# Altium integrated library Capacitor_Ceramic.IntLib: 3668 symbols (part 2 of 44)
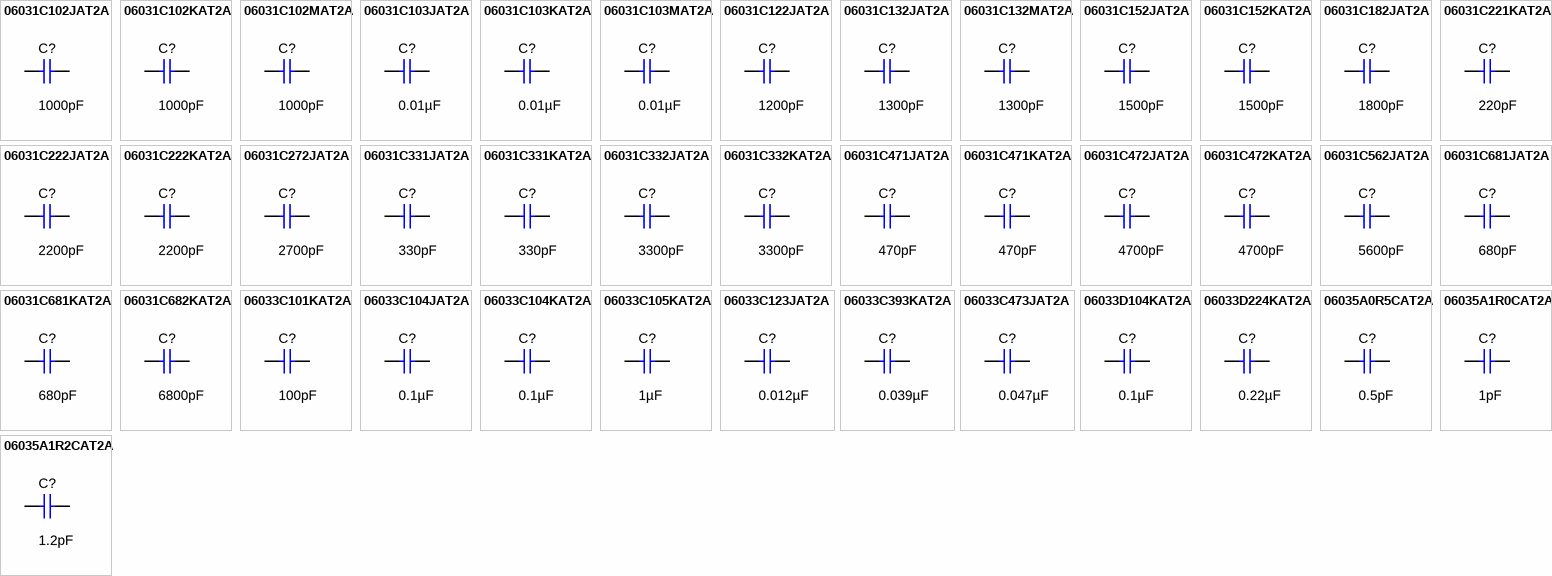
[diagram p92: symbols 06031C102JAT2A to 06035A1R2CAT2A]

## 06031C103MAT2A
designator C?  ValueDisplayed: 0.01µF  (hidden comment: 06031C103MAT2A)
CAP, CERM, 0.01 µF, 100 V,+/- 20%, X7R, 0603; Manufacturer: AVX; Polarized: N; CompType: Capacitor; Value: 0.01uF; U/M: EA; Cap_F: 0.00000001; Tolerance_%: 20; ESR_ohm: 0.098; Value1: 0.098 ohm; VDC_V: 100; Value2: 100V; TaMin_C: -55; TaMax_C: 125; Cap_Case: 0603; SizeArea_mm2: 1.28; SizeAreaWB_mm2: 4.68; SizeX_mm: 1.6; SizeY_mm: 0.8; SizeZ_mm: 1; AEC Category: Q200; Green_Lifecycle: Active; Green_REACh: Passed
signal-integrity model Cap
simulation model Cap
footprint 0603
footprint 0603M
footprint 0603L
footprint 0603_HV
footprint 0603S
pins: 1, 2

## 06031C122JAT2A
designator C?  ValueDisplayed: 1200pF  (hidden comment: 06031C122JAT2A)
CAP, CERM, 1200 pF, 100 V,+/- 5%, X7R, 0603; Manufacturer: AVX; Polarized: N; CompType: Capacitor; Value: 1200pF; U/M: EA; Cap_F: 0.0000000012; Tolerance_%: 5; ESR_ohm: 0.254; Value1: 0.254 ohm; VDC_V: 100; Value2: 100V; TaMin_C: -55; TaMax_C: 125; Cap_Case: 0603; SizeArea_mm2: 1.28; SizeAreaWB_mm2: 4.68; SizeX_mm: 1.6; SizeY_mm: 0.8; SizeZ_mm: 1; AEC Category: Q200; Green_Lifecycle: Not Set; Green_REACh: Incomplete
signal-integrity model Cap
simulation model Cap
footprint 0603
footprint 0603M
footprint 0603L
footprint 0603_HV
footprint 0603S
pins: 1, 2

## 06031C132JAT2A
designator C?  ValueDisplayed: 1300pF  (hidden comment: 06031C132JAT2A)
CAP, CERM, 1300 pF, 100 V,+/- 5%, X7R, 0603; Manufacturer: AVX; Polarized: N; CompType: Capacitor; Value: 1300pF; U/M: EA; Cap_F: 0.0000000013; Tolerance_%: 5; VDC_V: 100; Value2: 100V; TaMin_C: -55; TaMax_C: 125; Cap_Case: 0603; SizeArea_mm2: 1.28; SizeAreaWB_mm2: 4.68; SizeX_mm: 1.6; SizeY_mm: 0.8; SizeZ_mm: 1; AEC Category: Q200; Green_Lifecycle: Not Set; Green_REACh: Incomplete
signal-integrity model Cap
simulation model Cap
footprint 0603
footprint 0603M
footprint 0603L
footprint 0603_HV
footprint 0603S
pins: 1, 2

## 06031C132MAT2A
designator C?  ValueDisplayed: 1300pF  (hidden comment: 06031C132MAT2A)
CAP, CERM, 1300 pF, 100 V,+/- 20%, X7R, 0603; Manufacturer: AVX; Polarized: N; CompType: Capacitor; Value: 1300pF; U/M: EA; Cap_F: 0.0000000013; Tolerance_%: 20; VDC_V: 100; Value2: 100V; TaMin_C: -55; TaMax_C: 125; Cap_Case: 0603; SizeArea_mm2: 1.28; SizeAreaWB_mm2: 4.68; SizeX_mm: 1.6; SizeY_mm: 0.8; SizeZ_mm: 1; AEC Category: Q200; Green_Lifecycle: Not Set; Green_REACh: Incomplete
signal-integrity model Cap
simulation model Cap
footprint 0603
footprint 0603M
footprint 0603L
footprint 0603_HV
footprint 0603S
pins: 1, 2

## 06031C152JAT2A
designator C?  ValueDisplayed: 1500pF  (hidden comment: 06031C152JAT2A)
CAP, CERM, 1500 pF, 100 V,+/- 5%, X7R, 0603; Manufacturer: AVX; Polarized: N; CompType: Capacitor; Value: 1500pF; U/M: EA; Cap_F: 0.0000000015; Tolerance_%: 5; ESR_ohm: 0.229; Value1: 0.229 ohm; VDC_V: 100; Value2: 100V; TaMin_C: -55; TaMax_C: 125; Cap_Case: 0603; SizeArea_mm2: 1.28; SizeAreaWB_mm2: 4.68; SizeX_mm: 1.6; SizeY_mm: 0.8; SizeZ_mm: 1; AEC Category: Q200; Green_Lifecycle: Active; Green_REACh: Passed
signal-integrity model Cap
simulation model Cap
footprint 0603
footprint 0603M
footprint 0603L
footprint 0603_HV
footprint 0603S
pins: 1, 2

## 06031C152KAT2A
designator C?  ValueDisplayed: 1500pF  (hidden comment: 06031C152KAT2A)
CAP, CERM, 1500 pF, 100 V,+/- 10%, X7R, 0603; Manufacturer: AVX; Polarized: N; CompType: Capacitor; Value: 1500pF; U/M: EA; Cap_F: 0.0000000015; Tolerance_%: 10; ESR_ohm: 0.229; Value1: 0.229 ohm; VDC_V: 100; Value2: 100V; TaMin_C: -55; TaMax_C: 125; Cap_Case: 0603; SizeArea_mm2: 1.28; SizeAreaWB_mm2: 4.68; SizeX_mm: 1.6; SizeY_mm: 0.8; SizeZ_mm: 1; AEC Category: Q200; Green_Lifecycle: Not Set; Green_REACh: Incomplete
signal-integrity model Cap
simulation model Cap
footprint 0603
footprint 0603M
footprint 0603L
footprint 0603_HV
footprint 0603S
pins: 1, 2

## 06031C182JAT2A
designator C?  ValueDisplayed: 1800pF  (hidden comment: 06031C182JAT2A)
CAP, CERM, 1800 pF, 100 V,+/- 5%, X7R, 0603; Manufacturer: AVX; Polarized: N; CompType: Capacitor; Value: 1800pF; U/M: EA; Cap_F: 0.0000000018; Tolerance_%: 5; ESR_ohm: 0.21; Value1: 0.21 ohm; VDC_V: 100; Value2: 100V; TaMin_C: -55; TaMax_C: 125; Cap_Case: 0603; SizeArea_mm2: 1.28; SizeAreaWB_mm2: 4.68; SizeX_mm: 1.6; SizeY_mm: 0.8; SizeZ_mm: 1; AEC Category: Q200; Green_Lifecycle: Active; Green_REACh: Passed
signal-integrity model Cap
simulation model Cap
footprint 0603
footprint 0603M
footprint 0603L
footprint 0603_HV
footprint 0603S
pins: 1, 2

## 06031C221KAT2A
designator C?  ValueDisplayed: 220pF  (hidden comment: 06031C221KAT2A)
CAP, CERM, 220 pF, 100 V,+/- 10%, X7R, 0603; Manufacturer: AVX; Polarized: N; CompType: Capacitor; Value: 220pF; U/M: EA; Cap_F: 0.00000000022; Tolerance_%: 10; ESR_ohm: 0.579; Value1: 0.579 ohm; VDC_V: 100; Value2: 100V; TaMin_C: -55; TaMax_C: 125; Cap_Case: 0603; SizeArea_mm2: 1.28; SizeAreaWB_mm2: 4.68; SizeX_mm: 1.6; SizeY_mm: 0.8; SizeZ_mm: 1; AEC Category: Q200; Green_Lifecycle: Active; Green_REACh: Passed
signal-integrity model Cap
simulation model Cap
footprint 0603
footprint 0603M
footprint 0603L
footprint 0603_HV
footprint 0603S
pins: 1, 2

## 06031C222JAT2A
designator C?  ValueDisplayed: 2200pF  (hidden comment: 06031C222JAT2A)
CAP, CERM, 2200 pF, 100 V,+/- 5%, X7R, 0603; Manufacturer: AVX; Polarized: N; CompType: Capacitor; Value: 2200pF; U/M: EA; Cap_F: 0.0000000022; Tolerance_%: 5; ESR_ohm: 0.192; Value1: 0.192 ohm; VDC_V: 100; Value2: 100V; TaMin_C: -55; TaMax_C: 125; Cap_Case: 0603; SizeArea_mm2: 1.28; SizeAreaWB_mm2: 4.68; SizeX_mm: 1.6; SizeY_mm: 0.8; SizeZ_mm: 1; AEC Category: Q200; Green_Lifecycle: Active; Green_REACh: Passed
signal-integrity model Cap
simulation model Cap
footprint 0603
footprint 0603M
footprint 0603L
footprint 0603_HV
footprint 0603S
pins: 1, 2

## 06031C222KAT2A
designator C?  ValueDisplayed: 2200pF  (hidden comment: 06031C222KAT2A)
CAP, CERM, 2200 pF, 100 V,+/- 10%, X7R, 0603; Manufacturer: AVX; Polarized: N; CompType: Capacitor; Value: 2200pF; U/M: EA; Cap_F: 0.0000000022; Tolerance_%: 10; ESR_ohm: 0.192; Value1: 0.192 ohm; VDC_V: 100; Value2: 100V; TaMin_C: -55; TaMax_C: 125; Cap_Case: 0603; SizeArea_mm2: 1.28; SizeAreaWB_mm2: 4.68; SizeX_mm: 1.6; SizeY_mm: 0.8; SizeZ_mm: 1; AEC Category: Q200; Green_Lifecycle: Not Set; Green_REACh: Incomplete
signal-integrity model Cap
simulation model Cap
footprint 0603
footprint 0603M
footprint 0603L
footprint 0603_HV
footprint 0603S
pins: 1, 2

## 06031C272JAT2A
designator C?  ValueDisplayed: 2700pF  (hidden comment: 06031C272JAT2A)
CAP, CERM, 2700 pF, 100 V,+/- 5%, X7R, 0603; Manufacturer: AVX; Polarized: N; CompType: Capacitor; Value: 2700pF; U/M: EA; Cap_F: 0.0000000027; Tolerance_%: 5; ESR_ohm: 0.174; Value1: 0.174 ohm; VDC_V: 100; Value2: 100V; TaMin_C: -55; TaMax_C: 125; Cap_Case: 0603; SizeArea_mm2: 1.28; SizeAreaWB_mm2: 4.68; SizeX_mm: 1.6; SizeY_mm: 0.8; SizeZ_mm: 1; AEC Category: Q200; Green_Lifecycle: Active; Green_REACh: Passed
signal-integrity model Cap
simulation model Cap
footprint 0603
footprint 0603M
footprint 0603L
footprint 0603_HV
footprint 0603S
pins: 1, 2

## 06031C331JAT2A
designator C?  ValueDisplayed: 330pF  (hidden comment: 06031C331JAT2A)
CAP, CERM, 330 pF, 100 V,+/- 5%, X7R, 0603; Manufacturer: AVX; Polarized: N; CompType: Capacitor; Value: 330pF; U/M: EA; Cap_F: 0.00000000033; Tolerance_%: 5; ESR_ohm: 0.472; Value1: 0.472 ohm; VDC_V: 100; Value2: 100V; TaMin_C: -55; TaMax_C: 125; Cap_Case: 0603; SizeArea_mm2: 1.28; SizeAreaWB_mm2: 4.68; SizeX_mm: 1.6; SizeY_mm: 0.8; SizeZ_mm: 1; AEC Category: Q200; Green_Lifecycle: Active; Green_REACh: Passed
signal-integrity model Cap
simulation model Cap
footprint 0603
footprint 0603M
footprint 0603L
footprint 0603_HV
footprint 0603S
pins: 1, 2

## 06031C331KAT2A
designator C?  ValueDisplayed: 330pF  (hidden comment: 06031C331KAT2A)
CAP, CERM, 330 pF, 100 V,+/- 10%, X7R, 0603; Manufacturer: AVX; Polarized: N; CompType: Capacitor; Value: 330pF; U/M: EA; Cap_F: 0.00000000033; Tolerance_%: 10; ESR_ohm: 0.472; Value1: 0.472 ohm; VDC_V: 100; Value2: 100V; TaMin_C: -55; TaMax_C: 125; Cap_Case: 0603; SizeArea_mm2: 1.28; SizeAreaWB_mm2: 4.68; SizeX_mm: 1.6; SizeY_mm: 0.8; SizeZ_mm: 1; AEC Category: Q200; Green_Lifecycle: Active; Green_REACh: Passed
signal-integrity model Cap
simulation model Cap
footprint 0603
footprint 0603M
footprint 0603L
footprint 0603_HV
footprint 0603S
pins: 1, 2

## 06031C332JAT2A
designator C?  ValueDisplayed: 3300pF  (hidden comment: 06031C332JAT2A)
CAP, CERM, 3300 pF, 100 V,+/- 5%, X7R, 0603; Manufacturer: AVX; Polarized: N; CompType: Capacitor; Value: 3300pF; U/M: EA; Cap_F: 0.0000000033; Tolerance_%: 5; ESR_ohm: 0.159; Value1: 0.159 ohm; VDC_V: 100; Value2: 100V; TaMin_C: -55; TaMax_C: 125; Cap_Case: 0603; SizeArea_mm2: 1.28; SizeAreaWB_mm2: 4.68; SizeX_mm: 1.6; SizeY_mm: 0.8; SizeZ_mm: 1; AEC Category: Q200; Green_Lifecycle: Active; Green_REACh: Passed
signal-integrity model Cap
simulation model Cap
footprint 0603
footprint 0603M
footprint 0603L
footprint 0603_HV
footprint 0603S
pins: 1, 2

## 06031C332KAT2A
designator C?  ValueDisplayed: 3300pF  (hidden comment: 06031C332KAT2A)
CAP, CERM, 3300 pF, 100 V,+/- 10%, X7R, 0603; Manufacturer: AVX; Polarized: N; CompType: Capacitor; Value: 3300pF; U/M: EA; Cap_F: 0.0000000033; Tolerance_%: 10; ESR_ohm: 0.159; Value1: 0.159 ohm; VDC_V: 100; Value2: 100V; TaMin_C: -55; TaMax_C: 125; Cap_Case: 0603; SizeArea_mm2: 1.28; SizeAreaWB_mm2: 4.68; SizeX_mm: 1.6; SizeY_mm: 0.8; SizeZ_mm: 1; AEC Category: Q200; Green_Lifecycle: Active; Green_REACh: Passed
signal-integrity model Cap
simulation model Cap
footprint 0603
footprint 0603M
footprint 0603L
footprint 0603_HV
footprint 0603S
pins: 1, 2

## 06031C471JAT2A
designator C?  ValueDisplayed: 470pF  (hidden comment: 06031C471JAT2A)
CAP, CERM, 470 pF, 100 V,+/- 5%, X7R, 0603; Manufacturer: AVX; Polarized: N; CompType: Capacitor; Value: 470pF; U/M: EA; Cap_F: 0.00000000047; Tolerance_%: 5; ESR_ohm: 0.397; Value1: 0.397 ohm; VDC_V: 100; Value2: 100V; TaMin_C: -55; TaMax_C: 125; Cap_Case: 0603; SizeArea_mm2: 1.28; SizeAreaWB_mm2: 4.68; SizeX_mm: 1.6; SizeY_mm: 0.8; SizeZ_mm: 1; AEC Category: Q200; Green_Lifecycle: Active; Green_REACh: Passed
signal-integrity model Cap
simulation model Cap
footprint 0603
footprint 0603M
footprint 0603L
footprint 0603_HV
footprint 0603S
pins: 1, 2

## 06031C471KAT2A
designator C?  ValueDisplayed: 470pF  (hidden comment: 06031C471KAT2A)
CAP, CERM, 470 pF, 100 V,+/- 10%, X7R, 0603; Manufacturer: AVX; Polarized: N; CompType: Capacitor; Value: 470pF; U/M: EA; Cap_F: 0.00000000047; Tolerance_%: 10; ESR_ohm: 0.397; Value1: 0.397 ohm; VDC_V: 100; Value2: 100V; TaMin_C: -55; TaMax_C: 125; Cap_Case: 0603; SizeArea_mm2: 1.28; SizeAreaWB_mm2: 4.68; SizeX_mm: 1.6; SizeY_mm: 0.8; SizeZ_mm: 1; AEC Category: Q200; Green_Lifecycle: Not Set; Green_REACh: Incomplete
signal-integrity model Cap
simulation model Cap
footprint 0603
footprint 0603M
footprint 0603L
footprint 0603_HV
footprint 0603S
pins: 1, 2

## 06031C472JAT2A
designator C?  ValueDisplayed: 4700pF  (hidden comment: 06031C472JAT2A)
CAP, CERM, 4700 pF, 100 V,+/- 5%, X7R, 0603; Manufacturer: AVX; Polarized: N; CompType: Capacitor; Value: 4700pF; U/M: EA; Cap_F: 0.0000000047; Tolerance_%: 5; ESR_ohm: 0.136; Value1: 0.136 ohm; VDC_V: 100; Value2: 100V; TaMin_C: -55; TaMax_C: 125; Cap_Case: 0603; SizeArea_mm2: 1.28; SizeAreaWB_mm2: 4.68; SizeX_mm: 1.6; SizeY_mm: 0.8; SizeZ_mm: 1; AEC Category: Q200; Green_Lifecycle: Active; Green_REACh: Passed
signal-integrity model Cap
simulation model Cap
footprint 0603
footprint 0603M
footprint 0603L
footprint 0603_HV
footprint 0603S
pins: 1, 2

## 06031C472KAT2A
designator C?  ValueDisplayed: 4700pF  (hidden comment: 06031C472KAT2A)
CAP, CERM, 4700 pF, 100 V,+/- 10%, X7R, 0603; Manufacturer: AVX; Polarized: N; CompType: Capacitor; Value: 4700pF; U/M: EA; Cap_F: 0.0000000047; Tolerance_%: 10; ESR_ohm: 0.136; Value1: 0.136 ohm; VDC_V: 100; Value2: 100V; TaMin_C: -55; TaMax_C: 125; Cap_Case: 0603; SizeArea_mm2: 1.28; SizeAreaWB_mm2: 4.68; SizeX_mm: 1.6; SizeY_mm: 0.8; SizeZ_mm: 1; AEC Category: Q200; Green_Lifecycle: Active; Green_REACh: Passed
signal-integrity model Cap
simulation model Cap
footprint 0603
footprint 0603M
footprint 0603L
footprint 0603_HV
footprint 0603S
pins: 1, 2

## 06031C562JAT2A
designator C?  ValueDisplayed: 5600pF  (hidden comment: 06031C562JAT2A)
CAP, CERM, 5600 pF, 100 V,+/- 5%, X7R, 0603; Manufacturer: AVX; Polarized: N; CompType: Capacitor; Value: 5600pF; U/M: EA; Cap_F: 0.0000000056; Tolerance_%: 5; ESR_ohm: 0.125; Value1: 0.125 ohm; VDC_V: 100; Value2: 100V; TaMin_C: -55; TaMax_C: 125; Cap_Case: 0603; SizeArea_mm2: 1.28; SizeAreaWB_mm2: 4.68; SizeX_mm: 1.6; SizeY_mm: 0.8; SizeZ_mm: 1; AEC Category: Q200; Green_Lifecycle: Not Set; Green_REACh: Incomplete
signal-integrity model Cap
simulation model Cap
footprint 0603
footprint 0603M
footprint 0603L
footprint 0603_HV
footprint 0603S
pins: 1, 2

## 06031C681JAT2A
designator C?  ValueDisplayed: 680pF  (hidden comment: 06031C681JAT2A)
CAP, CERM, 680 pF, 100 V,+/- 5%, X7R, 0603; Manufacturer: AVX; Polarized: N; CompType: Capacitor; Value: 680pF; U/M: EA; Cap_F: 0.00000000068; Tolerance_%: 5; ESR_ohm: 0.332; Value1: 0.332 ohm; VDC_V: 100; Value2: 100V; TaMin_C: -55; TaMax_C: 125; Cap_Case: 0603; SizeArea_mm2: 1.28; SizeAreaWB_mm2: 4.68; SizeX_mm: 1.6; SizeY_mm: 0.8; SizeZ_mm: 1; AEC Category: Q200; Green_Lifecycle: Active; Green_REACh: Passed
signal-integrity model Cap
simulation model Cap
footprint 0603
footprint 0603M
footprint 0603L
footprint 0603_HV
footprint 0603S
pins: 1, 2

## 06031C681KAT2A
designator C?  ValueDisplayed: 680pF  (hidden comment: 06031C681KAT2A)
CAP, CERM, 680 pF, 100 V,+/- 10%, X7R, 0603; Manufacturer: AVX; Polarized: N; CompType: Capacitor; Value: 680pF; U/M: EA; Cap_F: 0.00000000068; Tolerance_%: 10; ESR_ohm: 0.332; Value1: 0.332 ohm; VDC_V: 100; Value2: 100V; TaMin_C: -55; TaMax_C: 125; Cap_Case: 0603; SizeArea_mm2: 1.28; SizeAreaWB_mm2: 4.68; SizeX_mm: 1.6; SizeY_mm: 0.8; SizeZ_mm: 1; AEC Category: Q200; Green_Lifecycle: Not Set; Green_REACh: Incomplete
signal-integrity model Cap
simulation model Cap
footprint 0603
footprint 0603M
footprint 0603L
footprint 0603_HV
footprint 0603S
pins: 1, 2

## 06031C682KAT2A
designator C?  ValueDisplayed: 6800pF  (hidden comment: 06031C682KAT2A)
CAP, CERM, 6800 pF, 100 V,+/- 10%, X7R, 0603; Manufacturer: AVX; Polarized: N; CompType: Capacitor; Value: 6800pF; U/M: EA; Cap_F: 0.0000000068; Tolerance_%: 10; ESR_ohm: 0.115; Value1: 0.115 ohm; VDC_V: 100; Value2: 100V; TaMin_C: -55; TaMax_C: 125; Cap_Case: 0603; SizeArea_mm2: 1.28; SizeAreaWB_mm2: 4.68; SizeX_mm: 1.6; SizeY_mm: 0.8; SizeZ_mm: 1; AEC Category: Q200; Green_Lifecycle: Not Set; Green_REACh: Incomplete
signal-integrity model Cap
simulation model Cap
footprint 0603
footprint 0603M
footprint 0603L
footprint 0603_HV
footprint 0603S
pins: 1, 2

## 06033C101KAT2A
designator C?  ValueDisplayed: 100pF  (hidden comment: 06033C101KAT2A)
CAP, CERM, 100 pF, 25 V,+/- 10%, X7R, 0603; Manufacturer: AVX; Polarized: N; CompType: Capacitor; Value: 100pF; U/M: EA; Cap_F: 0.0000000001; Tolerance_%: 10; VDC_V: 25; Value2: 25V; TaMin_C: -55; TaMax_C: 125; Cap_Case: 0603; SizeArea_mm2: 1.28; SizeAreaWB_mm2: 4.68; SizeX_mm: 1.6; SizeY_mm: 0.8; SizeZ_mm: 1; AEC Category: Q200; Green_Lifecycle: Active; Green_REACh: Passed
signal-integrity model Cap
simulation model Cap
footprint 0603
footprint 0603M
footprint 0603L
footprint 0603_HV
footprint 0603S
pins: 1, 2

## 06033C104JAT2A
designator C?  ValueDisplayed: 0.1µF  (hidden comment: 06033C104JAT2A)
CAP, CERM, 0.1 µF, 25 V,+/- 5%, X7R, 0603; Manufacturer: AVX; Polarized: N; CompType: Capacitor; Value: 0.1uF; U/M: EA; Cap_F: 0.0000001; Tolerance_%: 5; ESR_ohm: 0.05; Value1: 0.05 ohm; VDC_V: 25; Value2: 25V; TaMin_C: -55; TaMax_C: 125; Cap_Case: 0603; SizeArea_mm2: 1.28; SizeAreaWB_mm2: 4.68; SizeX_mm: 1.6; SizeY_mm: 0.8; SizeZ_mm: 1; AEC Category: Q200; Green_Lifecycle: Active; Green_REACh: Passed
signal-integrity model Cap
simulation model Cap
footprint 0603
footprint 0603M
footprint 0603L
footprint 0603_HV
footprint 0603S
pins: 1, 2

## 06033C104KAT2A
designator C?  ValueDisplayed: 0.1µF  (hidden comment: 06033C104KAT2A)
CAP, CERM, 0.1 µF, 25 V,+/- 10%, X7R, 0603; Manufacturer: AVX; Polarized: N; CompType: Capacitor; Value: 0.1uF; U/M: EA; Cap_F: 0.0000001; Tolerance_%: 10; ESR_ohm: 0.05; Value1: 0.05 ohm; VDC_V: 25; Value2: 25V; TaMin_C: -55; TaMax_C: 125; Cap_Case: 0603; SizeArea_mm2: 1.28; SizeAreaWB_mm2: 4.68; SizeX_mm: 1.6; SizeY_mm: 0.8; SizeZ_mm: 1; AEC Category: Q200; Green_Lifecycle: Active; Green_REACh: Passed
signal-integrity model Cap
simulation model Cap
footprint 0603
footprint 0603M
footprint 0603L
footprint 0603_HV
footprint 0603S
pins: 1, 2

## 06033C105KAT2A
designator C?  ValueDisplayed: 1µF  (hidden comment: 06033C105KAT2A)
CAP, CERM, 1 µF, 25 V,+/- 10%, X7R, 0603; Manufacturer: AVX; Polarized: N; CompType: Capacitor; Value: 1uF; U/M: EA; Cap_F: 0.000001; Tolerance_%: 10; VDC_V: 25; Value2: 25V; TaMin_C: -55; TaMax_C: 125; Cap_Case: 0603; SizeArea_mm2: 1.28; SizeAreaWB_mm2: 4.68; SizeX_mm: 1.6; SizeY_mm: 0.8; SizeZ_mm: 1; AEC Category: Q200
signal-integrity model Cap
simulation model Cap
footprint 0603
footprint 0603M
footprint 0603L
footprint 0603_HV
footprint 0603S
pins: 1, 2

## 06033C123JAT2A
designator C?  ValueDisplayed: 0.012µF  (hidden comment: 06033C123JAT2A)
CAP, CERM, 0.012 µF, 25 V,+/- 5%, X7R, 0603; Manufacturer: AVX; Polarized: N; CompType: Capacitor; Value: 0.012uF; U/M: EA; Cap_F: 0.000000012; Tolerance_%: 5; VDC_V: 25; Value2: 25V; TaMin_C: -55; TaMax_C: 125; Cap_Case: 0603; SizeArea_mm2: 1.28; SizeAreaWB_mm2: 4.68; SizeX_mm: 1.6; SizeY_mm: 0.8; SizeZ_mm: 1; AEC Category: Q200; Green_Lifecycle: Not Set; Green_REACh: Incomplete
signal-integrity model Cap
simulation model Cap
footprint 0603
footprint 0603M
footprint 0603L
footprint 0603_HV
footprint 0603S
pins: 1, 2

## 06033C393KAT2A
designator C?  ValueDisplayed: 0.039µF  (hidden comment: 06033C393KAT2A)
CAP, CERM, 0.039 µF, 25 V,+/- 10%, X7R, 0603; Manufacturer: AVX; Polarized: N; CompType: Capacitor; Value: 0.039uF; U/M: EA; Cap_F: 0.000000039; Tolerance_%: 10; ESR_ohm: 0.056; Value1: 0.056 ohm; VDC_V: 25; Value2: 25V; TaMin_C: -55; TaMax_C: 125; Cap_Case: 0603; SizeArea_mm2: 1.28; SizeAreaWB_mm2: 4.68; SizeX_mm: 1.6; SizeY_mm: 0.8; SizeZ_mm: 1; AEC Category: Q200; Green_Lifecycle: Active; Green_REACh: Passed
signal-integrity model Cap
simulation model Cap
footprint 0603
footprint 0603M
footprint 0603L
footprint 0603_HV
footprint 0603S
pins: 1, 2

## 06033C473JAT2A
designator C?  ValueDisplayed: 0.047µF  (hidden comment: 06033C473JAT2A)
CAP, CERM, 0.047 µF, 25 V,+/- 5%, X7R, 0603; Manufacturer: AVX; Polarized: N; CompType: Capacitor; Value: 0.047uF; U/M: EA; Cap_F: 0.000000047; Tolerance_%: 5; ESR_ohm: 0.052; Value1: 0.052 ohm; VDC_V: 25; Value2: 25V; TaMin_C: -55; TaMax_C: 125; Cap_Case: 0603; SizeArea_mm2: 1.28; SizeAreaWB_mm2: 4.68; SizeX_mm: 1.6; SizeY_mm: 0.8; SizeZ_mm: 1; AEC Category: Q200; Green_Lifecycle: Active; Green_REACh: Passed
signal-integrity model Cap
simulation model Cap
footprint 0603
footprint 0603M
footprint 0603L
footprint 0603_HV
footprint 0603S
pins: 1, 2

## 06033D104KAT2A
designator C?  ValueDisplayed: 0.1µF  (hidden comment: 06033D104KAT2A)
CAP, CERM, 0.1 µF, 25 V,+/- 10%, X5R, 0603; Manufacturer: AVX; Polarized: N; CompType: Capacitor; Value: 0.1uF; U/M: EA; Cap_F: 0.0000001; Tolerance_%: 10; ESR_ohm: 0.048; Value1: 0.048 ohm; VDC_V: 25; Value2: 25V; IRMS_A: 0.53; TaMin_C: -55; TaMax_C: 85; Cap_Case: 0603; SizeArea_mm2: 1.28; SizeAreaWB_mm2: 4.68; SizeX_mm: 1.6; SizeY_mm: 0.8; SizeZ_mm: 1; AEC Category: Q200; Green_Lifecycle: Active; Green_REACh: Passed
signal-integrity model Cap
simulation model Cap
footprint 0603
footprint 0603M
footprint 0603L
footprint 0603_HV
footprint 0603S
pins: 1, 2

## 06033D224KAT2A
designator C?  ValueDisplayed: 0.22µF  (hidden comment: 06033D224KAT2A)
CAP, CERM, 0.22 µF, 25 V,+/- 10%, X5R, 0603; Manufacturer: AVX; Polarized: N; CompType: Capacitor; Value: 0.22uF; U/M: EA; Cap_F: 0.00000022; Tolerance_%: 10; ESR_ohm: 0.036; Value1: 0.036 ohm; VDC_V: 25; Value2: 25V; TaMin_C: -55; TaMax_C: 85; Cap_Case: 0603; SizeArea_mm2: 1.28; SizeAreaWB_mm2: 4.68; SizeX_mm: 1.6; SizeY_mm: 0.8; SizeZ_mm: 1; AEC Category: Q200; Green_Lifecycle: Active; Green_REACh: Passed
signal-integrity model Cap
simulation model Cap
footprint 0603
footprint 0603M
footprint 0603L
footprint 0603_HV
footprint 0603S
pins: 1, 2

## 06035A0R5CAT2A
designator C?  ValueDisplayed: 0.5pF  (hidden comment: 06035A0R5CAT2A)
CAP, CERM, 0.5 pF, 50 V,+/- 50%, C0G/NP0, 0603; Manufacturer: AVX; Polarized: N; CompType: Capacitor; Value: 0.5pF; U/M: EA; Cap_F: 0.0000000000005; Tolerance_%: 50; ESR_ohm: 2.972; Value1: 2.972 ohm; Value2: 50V; TaMin_C: -55; TaMax_C: 125; Cap_Case: 0603; SizeArea_mm2: 1.28; SizeAreaWB_mm2: 4.68; SizeX_mm: 1.6; SizeY_mm: 0.8; SizeZ_mm: 1; AEC Category: Q200; Green_Lifecycle: Not Set; Green_REACh: Incomplete
signal-integrity model Cap
simulation model Cap
footprint 0603
footprint 0603M
footprint 0603L
footprint 0603_HV
footprint 0603S
pins: 1, 2

## 06035A1R0CAT2A
designator C?  ValueDisplayed: 1pF  (hidden comment: 06035A1R0CAT2A)
CAP, CERM, 1 pF, 50 V,+/- 25%, C0G/NP0, 0603; Manufacturer: AVX; Polarized: N; CompType: Capacitor; Value: 1pF; U/M: EA; Cap_F: 0.000000000001; Tolerance_%: 25; ESR_ohm: 1.782; Value1: 1.782 ohm; VDC_V: 50; Value2: 50V; TaMin_C: -55; TaMax_C: 125; Cap_Case: 0603; SizeArea_mm2: 1.28; SizeAreaWB_mm2: 4.68; SizeX_mm: 1.6; SizeY_mm: 0.8; SizeZ_mm: 1; AEC Category: Q200; Green_Lifecycle: Active; Green_REACh: Passed
signal-integrity model Cap
simulation model Cap
footprint 0603
footprint 0603M
footprint 0603L
footprint 0603_HV
footprint 0603S
pins: 1, 2

## 06035A1R2CAT2A
designator C?  ValueDisplayed: 1.2pF  (hidden comment: 06035A1R2CAT2A)
CAP, CERM, 1.2 pF, 50 V,+/- 21%, C0G/NP0, 0603; Manufacturer: AVX; Polarized: N; CompType: Capacitor; Value: 1.2pF; U/M: EA; Cap_F: 0.0000000000012; Tolerance_%: 21; ESR_ohm: 1.566; Value1: 1.566 ohm; VDC_V: 50; Value2: 50V; TaMin_C: -55; TaMax_C: 125; Cap_Case: 0603; SizeArea_mm2: 1.28; SizeAreaWB_mm2: 4.68; SizeX_mm: 1.6; SizeY_mm: 0.8; SizeZ_mm: 1; AEC Category: Q200; Green_Lifecycle: Not Set; Green_REACh: Incomplete
signal-integrity model Cap
simulation model Cap
footprint 0603
footprint 0603M
footprint 0603L
footprint 0603_HV
footprint 0603S
pins: 1, 2

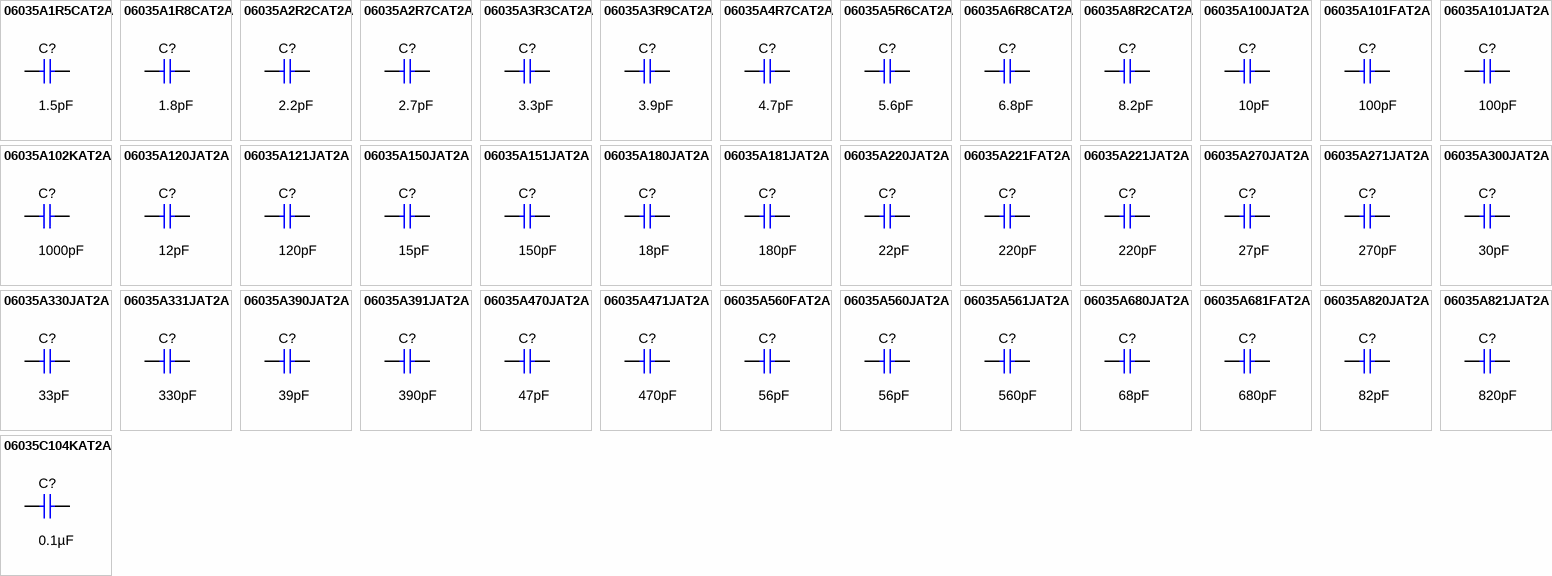
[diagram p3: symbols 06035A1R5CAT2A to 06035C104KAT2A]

## 06035A1R5CAT2A
designator C?  ValueDisplayed: 1.5pF  (hidden comment: 06035A1R5CAT2A)
CAP, CERM, 1.5 pF, 50 V,+/- 17%, C0G/NP0, 0603; Manufacturer: AVX; Polarized: N; CompType: Capacitor; Value: 1.5pF; U/M: EA; Cap_F: 0.0000000000015; Tolerance_%: 17; ESR_ohm: 1.34; Value1: 1.34 ohm; VDC_V: 50; Value2: 50V; TaMin_C: -55; TaMax_C: 125; Cap_Case: 0603; SizeArea_mm2: 1.28; SizeAreaWB_mm2: 4.68; SizeX_mm: 1.6; SizeY_mm: 0.8; SizeZ_mm: 1; AEC Category: Q200; Green_Lifecycle: Not Set; Green_REACh: Incomplete
signal-integrity model Cap
simulation model Cap
footprint 0603
footprint 0603M
footprint 0603L
footprint 0603_HV
footprint 0603S
pins: 1, 2

## 06035A1R8CAT2A
designator C?  ValueDisplayed: 1.8pF  (hidden comment: 06035A1R8CAT2A)
CAP, CERM, 1.8 pF, 50 V,+/- 14%, C0G/NP0, 0603; Manufacturer: AVX; Polarized: N; CompType: Capacitor; Value: 1.8pF; U/M: EA; Cap_F: 0.0000000000018; Tolerance_%: 14; ESR_ohm: 1.182; Value1: 1.182 ohm; VDC_V: 50; Value2: 50V; TaMin_C: -55; TaMax_C: 125; Cap_Case: 0603; SizeArea_mm2: 1.28; SizeAreaWB_mm2: 4.68; SizeX_mm: 1.6; SizeY_mm: 0.8; SizeZ_mm: 1; AEC Category: Q200; Green_Lifecycle: Not Set; Green_REACh: Incomplete
signal-integrity model Cap
simulation model Cap
footprint 0603
footprint 0603M
footprint 0603L
footprint 0603_HV
footprint 0603S
pins: 1, 2

## 06035A2R2CAT2A
designator C?  ValueDisplayed: 2.2pF  (hidden comment: 06035A2R2CAT2A)
CAP, CERM, 2.2 pF, 50 V,+/- 11%, C0G/NP0, 0603; Manufacturer: AVX; Polarized: N; CompType: Capacitor; Value: 2.2pF; U/M: EA; Cap_F: 0.0000000000022; Tolerance_%: 11; ESR_ohm: 1.033; Value1: 1.033 ohm; VDC_V: 50; Value2: 50V; TaMin_C: -55; TaMax_C: 125; Cap_Case: 0603; SizeArea_mm2: 1.28; SizeAreaWB_mm2: 4.68; SizeX_mm: 1.6; SizeY_mm: 0.8; SizeZ_mm: 1; AEC Category: Q200; Green_Lifecycle: Not Set; Green_REACh: Incomplete
signal-integrity model Cap
simulation model Cap
footprint 0603
footprint 0603M
footprint 0603L
footprint 0603_HV
footprint 0603S
pins: 1, 2

## 06035A2R7CAT2A
designator C?  ValueDisplayed: 2.7pF  (hidden comment: 06035A2R7CAT2A)
CAP, CERM, 2.7 pF, 50 V,+/- 9%, C0G/NP0, 0603; Manufacturer: AVX; Polarized: N; CompType: Capacitor; Value: 2.7pF; U/M: EA; Cap_F: 0.0000000000027; Tolerance_%: 9; ESR_ohm: 0.902; Value1: 0.902 ohm; VDC_V: 50; Value2: 50V; TaMin_C: -55; TaMax_C: 125; Cap_Case: 0603; SizeArea_mm2: 1.28; SizeAreaWB_mm2: 4.68; SizeX_mm: 1.6; SizeY_mm: 0.8; SizeZ_mm: 1; AEC Category: Q200; Green_Lifecycle: Not Set; Green_REACh: Incomplete
signal-integrity model Cap
simulation model Cap
footprint 0603
footprint 0603M
footprint 0603L
footprint 0603_HV
footprint 0603S
pins: 1, 2

## 06035A3R3CAT2A
designator C?  ValueDisplayed: 3.3pF  (hidden comment: 06035A3R3CAT2A)
CAP, CERM, 3.3 pF, 50 V,+/- 8%, C0G/NP0, 0603; Manufacturer: AVX; Polarized: N; CompType: Capacitor; Value: 3.3pF; U/M: EA; Cap_F: 0.0000000000033; Tolerance_%: 8; ESR_ohm: 0.792; Value1: 0.792 ohm; VDC_V: 50; Value2: 50V; TaMin_C: -55; TaMax_C: 125; Cap_Case: 0603; SizeArea_mm2: 1.28; SizeAreaWB_mm2: 4.68; SizeX_mm: 1.6; SizeY_mm: 0.8; SizeZ_mm: 1; AEC Category: Q200; Green_Lifecycle: Not Set; Green_REACh: Incomplete
signal-integrity model Cap
simulation model Cap
footprint 0603
footprint 0603M
footprint 0603L
footprint 0603_HV
footprint 0603S
pins: 1, 2

## 06035A3R9CAT2A
designator C?  ValueDisplayed: 3.9pF  (hidden comment: 06035A3R9CAT2A)
CAP, CERM, 3.9 pF, 50 V,+/- 6%, C0G/NP0, 0603; Manufacturer: AVX; Polarized: N; CompType: Capacitor; Value: 3.9pF; U/M: EA; Cap_F: 0.0000000000039; Tolerance_%: 6; ESR_ohm: 0.712; Value1: 0.712 ohm; VDC_V: 50; Value2: 50V; TaMin_C: -55; TaMax_C: 125; Cap_Case: 0603; SizeArea_mm2: 1.28; SizeAreaWB_mm2: 4.68; SizeX_mm: 1.6; SizeY_mm: 0.8; SizeZ_mm: 1; AEC Category: Q200; Green_Lifecycle: Not Set; Green_REACh: Incomplete
signal-integrity model Cap
simulation model Cap
footprint 0603
footprint 0603M
footprint 0603L
footprint 0603_HV
footprint 0603S
pins: 1, 2

## 06035A4R7CAT2A
designator C?  ValueDisplayed: 4.7pF  (hidden comment: 06035A4R7CAT2A)
CAP, CERM, 4.7 pF, 50 V,+/- 5%, C0G/NP0, 0603; Manufacturer: AVX; Polarized: N; CompType: Capacitor; Value: 4.7pF; U/M: EA; Cap_F: 0.0000000000047; Tolerance_%: 5; ESR_ohm: 0.633; Value1: 0.633 ohm; VDC_V: 50; Value2: 50V; TaMin_C: -55; TaMax_C: 125; Cap_Case: 0603; SizeArea_mm2: 1.28; SizeAreaWB_mm2: 4.68; SizeX_mm: 1.6; SizeY_mm: 0.8; SizeZ_mm: 1; AEC Category: Q200; Green_Lifecycle: Active; Green_REACh: Passed
signal-integrity model Cap
simulation model Cap
footprint 0603
footprint 0603M
footprint 0603L
footprint 0603_HV
footprint 0603S
pins: 1, 2

## 06035A5R6CAT2A
designator C?  ValueDisplayed: 5.6pF  (hidden comment: 06035A5R6CAT2A)
CAP, CERM, 5.6 pF, 50 V,+/- 5%, C0G/NP0, 0603; Manufacturer: AVX; Polarized: N; CompType: Capacitor; Value: 5.6pF; U/M: EA; Cap_F: 0.0000000000056; Tolerance_%: 5; ESR_ohm: 0.568; Value1: 0.568 ohm; VDC_V: 50; Value2: 50V; TaMin_C: -55; TaMax_C: 125; Cap_Case: 0603; SizeArea_mm2: 1.28; SizeAreaWB_mm2: 4.68; SizeX_mm: 1.6; SizeY_mm: 0.8; SizeZ_mm: 1; AEC Category: Q200; Green_Lifecycle: Not Set; Green_REACh: Incomplete
signal-integrity model Cap
simulation model Cap
footprint 0603
footprint 0603M
footprint 0603L
footprint 0603_HV
footprint 0603S
pins: 1, 2

## 06035A6R8CAT2A
designator C?  ValueDisplayed: 6.8pF  (hidden comment: 06035A6R8CAT2A)
CAP, CERM, 6.8 pF, 50 V,+/- 4%, C0G/NP0, 0603; Manufacturer: AVX; Polarized: N; CompType: Capacitor; Value: 6.8pF; U/M: EA; Cap_F: 0.0000000000068; Tolerance_%: 4; ESR_ohm: 0.505; Value1: 0.505 ohm; VDC_V: 50; Value2: 50V; TaMin_C: -55; TaMax_C: 125; Cap_Case: 0603; SizeArea_mm2: 1.28; SizeAreaWB_mm2: 4.68; SizeX_mm: 1.6; SizeY_mm: 0.8; SizeZ_mm: 1; AEC Category: Q200; Green_Lifecycle: Active; Green_REACh: Passed
signal-integrity model Cap
simulation model Cap
footprint 0603
footprint 0603M
footprint 0603L
footprint 0603_HV
footprint 0603S
pins: 1, 2

## 06035A8R2CAT2A
designator C?  ValueDisplayed: 8.2pF  (hidden comment: 06035A8R2CAT2A)
CAP, CERM, 8.2 pF, 50 V,+/- 3%, C0G/NP0, 0603; Manufacturer: AVX; Polarized: N; CompType: Capacitor; Value: 8.2pF; U/M: EA; Cap_F: 0.0000000000082; Tolerance_%: 3; ESR_ohm: 0.452; Value1: 0.452 ohm; VDC_V: 50; Value2: 50V; TaMin_C: -55; TaMax_C: 125; Cap_Case: 0603; SizeArea_mm2: 1.28; SizeAreaWB_mm2: 4.68; SizeX_mm: 1.6; SizeY_mm: 0.8; SizeZ_mm: 1; AEC Category: Q200; Green_Lifecycle: Active; Green_REACh: Passed
signal-integrity model Cap
simulation model Cap
footprint 0603
footprint 0603M
footprint 0603L
footprint 0603_HV
footprint 0603S
pins: 1, 2

## 06035A100JAT2A
designator C?  ValueDisplayed: 10pF  (hidden comment: 06035A100JAT2A)
CAP, CERM, 10 pF, 50 V,+/- 5%, C0G/NP0, 0603; Manufacturer: AVX; Polarized: N; CompType: Capacitor; Value: 10pF; U/M: EA; Cap_F: 0.00000000001; Tolerance_%: 5; ESR_ohm: 0.403; Value1: 0.403 ohm; VDC_V: 50; Value2: 50V; TaMin_C: -55; TaMax_C: 125; Cap_Case: 0603; SizeArea_mm2: 1.28; SizeAreaWB_mm2: 4.68; SizeX_mm: 1.6; SizeY_mm: 0.8; SizeZ_mm: 1; AEC Category: Q200; Green_Lifecycle: Active; Green_REACh: Passed
signal-integrity model Cap
simulation model Cap
footprint 0603
footprint 0603M
footprint 0603L
footprint 0603_HV
footprint 0603S
pins: 1, 2

## 06035A101FAT2A
designator C?  ValueDisplayed: 100pF  (hidden comment: 06035A101FAT2A)
CAP, CERM, 100 pF, 50 V,+/- 1%, C0G/NP0, 0603; Manufacturer: AVX; Polarized: N; CompType: Capacitor; Value: 100pF; U/M: EA; Cap_F: 0.0000000001; Tolerance_%: 1; VDC_V: 50; Value2: 50V; TaMin_C: -55; TaMax_C: 125; Cap_Case: 0603; SizeArea_mm2: 1.28; SizeAreaWB_mm2: 4.68; SizeX_mm: 1.6; SizeY_mm: 0.8; AEC Category: Q200; Green_Lifecycle: Active; Green_REACh: Passed
signal-integrity model Cap
simulation model Cap
footprint 0603
footprint 0603M
footprint 0603L
footprint 0603_HV
footprint 0603S
pins: 1, 2

## 06035A101JAT2A
designator C?  ValueDisplayed: 100pF  (hidden comment: 06035A101JAT2A)
CAP, CERM, 100 pF, 50 V,+/- 5%, C0G/NP0, 0603; Manufacturer: AVX; Polarized: N; CompType: Capacitor; Value: 100pF; U/M: EA; Cap_F: 0.0000000001; Tolerance_%: 5; ESR_ohm: 0.119; Value1: 0.119 ohm; VDC_V: 50; Value2: 50V; TaMin_C: -55; TaMax_C: 125; Cap_Case: 0603; SizeArea_mm2: 1.28; SizeAreaWB_mm2: 4.68; SizeX_mm: 1.6; SizeY_mm: 0.8; SizeZ_mm: 1; AEC Category: Q200; Green_Lifecycle: Active; Green_REACh: Passed
signal-integrity model Cap
simulation model Cap
footprint 0603
footprint 0603M
footprint 0603L
footprint 0603_HV
footprint 0603S
pins: 1, 2

## 06035A102KAT2A
designator C?  ValueDisplayed: 1000pF  (hidden comment: 06035A102KAT2A)
CAP, CERM, 1000 pF, 50 V,+/- 10%, C0G/NP0, 0603; Manufacturer: AVX; Polarized: N; CompType: Capacitor; Value: 1000pF; U/M: EA; Cap_F: 0.000000001; Tolerance_%: 10; ESR_ohm: 0.048; Value1: 0.048 ohm; VDC_V: 50; Value2: 50V; TaMin_C: -55; TaMax_C: 125; Cap_Case: 0603; SizeArea_mm2: 1.28; SizeAreaWB_mm2: 4.68; SizeX_mm: 1.6; SizeY_mm: 0.8; SizeZ_mm: 1; AEC Category: Q200; Green_Lifecycle: Active; Green_REACh: Passed
signal-integrity model Cap
simulation model Cap
footprint 0603
footprint 0603M
footprint 0603L
footprint 0603_HV
footprint 0603S
pins: 1, 2

## 06035A120JAT2A
designator C?  ValueDisplayed: 12pF  (hidden comment: 06035A120JAT2A)
CAP, CERM, 12 pF, 50 V,+/- 5%, C0G/NP0, 0603; Manufacturer: AVX; Polarized: N; CompType: Capacitor; Value: 12pF; U/M: EA; Cap_F: 0.000000000012; Tolerance_%: 5; ESR_ohm: 0.363; Value1: 0.363 ohm; VDC_V: 50; Value2: 50V; TaMin_C: -55; TaMax_C: 125; Cap_Case: 0603; SizeArea_mm2: 1.28; SizeAreaWB_mm2: 4.68; SizeX_mm: 1.6; SizeY_mm: 0.8; SizeZ_mm: 1; AEC Category: Q200; Green_Lifecycle: Active; Green_REACh: Passed
signal-integrity model Cap
simulation model Cap
footprint 0603
footprint 0603M
footprint 0603L
footprint 0603_HV
footprint 0603S
pins: 1, 2

## 06035A121JAT2A
designator C?  ValueDisplayed: 120pF  (hidden comment: 06035A121JAT2A)
CAP, CERM, 120 pF, 50 V,+/- 5%, C0G/NP0, 0603; Manufacturer: AVX; Polarized: N; CompType: Capacitor; Value: 120pF; U/M: EA; Cap_F: 0.00000000012; Tolerance_%: 5; ESR_ohm: 0.109; Value1: 0.109 ohm; VDC_V: 50; Value2: 50V; TaMin_C: -55; TaMax_C: 125; Cap_Case: 0603; SizeArea_mm2: 1.28; SizeAreaWB_mm2: 4.68; SizeX_mm: 1.6; SizeY_mm: 0.8; SizeZ_mm: 1; AEC Category: Q200; Green_Lifecycle: Active; Green_REACh: Passed
signal-integrity model Cap
simulation model Cap
footprint 0603
footprint 0603M
footprint 0603L
footprint 0603_HV
footprint 0603S
pins: 1, 2

## 06035A150JAT2A
designator C?  ValueDisplayed: 15pF  (hidden comment: 06035A150JAT2A)
CAP, CERM, 15 pF, 50 V,+/- 5%, C0G/NP0, 0603; Manufacturer: AVX; Polarized: N; CompType: Capacitor; Value: 15pF; U/M: EA; Cap_F: 0.000000000015; Tolerance_%: 5; ESR_ohm: 0.32; Value1: 0.32 ohm; VDC_V: 50; Value2: 50V; TaMin_C: -55; TaMax_C: 125; Cap_Case: 0603; SizeArea_mm2: 1.28; SizeAreaWB_mm2: 4.68; SizeX_mm: 1.6; SizeY_mm: 0.8; SizeZ_mm: 1; AEC Category: Q200; Green_Lifecycle: Active; Green_REACh: Passed
signal-integrity model Cap
simulation model Cap
footprint 0603
footprint 0603M
footprint 0603L
footprint 0603_HV
footprint 0603S
pins: 1, 2

## 06035A151JAT2A
designator C?  ValueDisplayed: 150pF  (hidden comment: 06035A151JAT2A)
CAP, CERM, 150 pF, 50 V,+/- 5%, C0G/NP0, 0603; Manufacturer: AVX; Polarized: N; CompType: Capacitor; Value: 150pF; U/M: EA; Cap_F: 0.00000000015; Tolerance_%: 5; ESR_ohm: 0.098; Value1: 0.098 ohm; VDC_V: 50; Value2: 50V; TaMin_C: -55; TaMax_C: 125; Cap_Case: 0603; SizeArea_mm2: 1.28; SizeAreaWB_mm2: 4.68; SizeX_mm: 1.6; SizeY_mm: 0.8; SizeZ_mm: 1; AEC Category: Q200; Green_Lifecycle: Not Set; Green_REACh: Incomplete
signal-integrity model Cap
simulation model Cap
footprint 0603
footprint 0603M
footprint 0603L
footprint 0603_HV
footprint 0603S
pins: 1, 2

## 06035A180JAT2A
designator C?  ValueDisplayed: 18pF  (hidden comment: 06035A180JAT2A)
CAP, CERM, 18 pF, 50 V,+/- 5%, C0G/NP0, 0603; Manufacturer: AVX; Polarized: N; CompType: Capacitor; Value: 18pF; U/M: EA; Cap_F: 0.000000000018; Tolerance_%: 5; ESR_ohm: 0.289; Value1: 0.289 ohm; VDC_V: 50; Value2: 50V; TaMin_C: -55; TaMax_C: 125; Cap_Case: 0603; SizeArea_mm2: 1.28; SizeAreaWB_mm2: 4.68; SizeX_mm: 1.6; SizeY_mm: 0.8; SizeZ_mm: 1; AEC Category: Q200; Green_Lifecycle: Not Set; Green_REACh: Incomplete
signal-integrity model Cap
simulation model Cap
footprint 0603
footprint 0603M
footprint 0603L
footprint 0603_HV
footprint 0603S
pins: 1, 2

## 06035A181JAT2A
designator C?  ValueDisplayed: 180pF  (hidden comment: 06035A181JAT2A)
CAP, CERM, 180 pF, 50 V,+/- 5%, C0G/NP0, 0603; Manufacturer: AVX; Polarized: N; CompType: Capacitor; Value: 180pF; U/M: EA; Cap_F: 0.00000000018; Tolerance_%: 5; ESR_ohm: 0.09; Value1: 0.09 ohm; VDC_V: 50; Value2: 50V; TaMin_C: -55; TaMax_C: 125; Cap_Case: 0603; SizeArea_mm2: 1.28; SizeAreaWB_mm2: 4.68; SizeX_mm: 1.6; SizeY_mm: 0.8; SizeZ_mm: 1; AEC Category: Q200; Green_Lifecycle: Not Set; Green_REACh: Incomplete
signal-integrity model Cap
simulation model Cap
footprint 0603
footprint 0603M
footprint 0603L
footprint 0603_HV
footprint 0603S
pins: 1, 2

## 06035A220JAT2A
designator C?  ValueDisplayed: 22pF  (hidden comment: 06035A220JAT2A)
CAP, CERM, 22 pF, 50 V,+/- 5%, C0G/NP0, 0603; Manufacturer: AVX; Polarized: N; CompType: Capacitor; Value: 22pF; U/M: EA; Cap_F: 0.000000000022; Tolerance_%: 5; ESR_ohm: 0.259; Value1: 0.259 ohm; VDC_V: 50; Value2: 50V; TaMin_C: -55; TaMax_C: 125; Cap_Case: 0603; SizeArea_mm2: 1.28; SizeAreaWB_mm2: 4.68; SizeX_mm: 1.6; SizeY_mm: 0.8; SizeZ_mm: 1; AEC Category: Q200; Green_Lifecycle: Active; Green_REACh: Passed
signal-integrity model Cap
simulation model Cap
footprint 0603
footprint 0603M
footprint 0603L
footprint 0603_HV
footprint 0603S
pins: 1, 2

## 06035A221FAT2A
designator C?  ValueDisplayed: 220pF  (hidden comment: 06035A221FAT2A)
CAP, CERM, 220 pF, 50 V,+/- 1%, C0G/NP0, 0603; Manufacturer: AVX; Polarized: N; CompType: Capacitor; Value: 220pF; U/M: EA; Cap_F: 0.00000000022; Tolerance_%: 1; ESR_ohm: 0.083; Value1: 0.083 ohm; VDC_V: 50; Value2: 50V; TaMin_C: -55; TaMax_C: 125; Cap_Case: 0603; SizeArea_mm2: 1.28; SizeAreaWB_mm2: 4.68; SizeX_mm: 1.6; SizeY_mm: 0.8; AEC Category: Q200; Green_Lifecycle: Active; Green_REACh: Passed
signal-integrity model Cap
simulation model Cap
footprint 0603
footprint 0603M
footprint 0603L
footprint 0603_HV
footprint 0603S
pins: 1, 2

## 06035A221JAT2A
designator C?  ValueDisplayed: 220pF  (hidden comment: 06035A221JAT2A)
CAP, CERM, 220 pF, 50 V,+/- 5%, C0G/NP0, 0603; Manufacturer: AVX; Polarized: N; CompType: Capacitor; Value: 220pF; U/M: EA; Cap_F: 0.00000000022; Tolerance_%: 5; ESR_ohm: 0.083; Value1: 0.083 ohm; VDC_V: 50; Value2: 50V; TaMin_C: -55; TaMax_C: 125; Cap_Case: 0603; SizeArea_mm2: 1.28; SizeAreaWB_mm2: 4.68; SizeX_mm: 1.6; SizeY_mm: 0.8; SizeZ_mm: 1; AEC Category: Q200; Green_Lifecycle: Not Set; Green_REACh: Incomplete
signal-integrity model Cap
simulation model Cap
footprint 0603
footprint 0603M
footprint 0603L
footprint 0603_HV
footprint 0603S
pins: 1, 2

## 06035A270JAT2A
designator C?  ValueDisplayed: 27pF  (hidden comment: 06035A270JAT2A)
CAP, CERM, 27 pF, 50 V,+/- 5%, C0G/NP0, 0603; Manufacturer: AVX; Polarized: N; CompType: Capacitor; Value: 27pF; U/M: EA; Cap_F: 0.000000000027; Tolerance_%: 5; ESR_ohm: 0.232; Value1: 0.232 ohm; VDC_V: 50; Value2: 50V; TaMin_C: -55; TaMax_C: 125; Cap_Case: 0603; SizeArea_mm2: 1.28; SizeAreaWB_mm2: 4.68; SizeX_mm: 1.6; SizeY_mm: 0.8; SizeZ_mm: 1; AEC Category: Q200; Green_Lifecycle: Active; Green_REACh: Passed
signal-integrity model Cap
simulation model Cap
footprint 0603
footprint 0603M
footprint 0603L
footprint 0603_HV
footprint 0603S
pins: 1, 2

## 06035A271JAT2A
designator C?  ValueDisplayed: 270pF  (hidden comment: 06035A271JAT2A)
CAP, CERM, 270 pF, 50 V,+/- 5%, C0G/NP0, 0603; Manufacturer: AVX; Polarized: N; CompType: Capacitor; Value: 270pF; U/M: EA; Cap_F: 0.00000000027; Tolerance_%: 5; ESR_ohm: 0.077; Value1: 0.077 ohm; VDC_V: 50; Value2: 50V; TaMin_C: -55; TaMax_C: 125; Cap_Case: 0603; SizeArea_mm2: 1.28; SizeAreaWB_mm2: 4.68; SizeX_mm: 1.6; SizeY_mm: 0.8; SizeZ_mm: 1; AEC Category: Q200; Green_Lifecycle: Not Set; Green_REACh: Incomplete
signal-integrity model Cap
simulation model Cap
footprint 0603
footprint 0603M
footprint 0603L
footprint 0603_HV
footprint 0603S
pins: 1, 2

## 06035A300JAT2A
designator C?  ValueDisplayed: 30pF  (hidden comment: 06035A300JAT2A)
CAP, CERM, 30 pF, 50 V,+/- 5%, C0G/NP0, 0603; Manufacturer: AVX; Polarized: N; CompType: Capacitor; Value: 30pF; U/M: EA; Cap_F: 0.00000000003; Tolerance_%: 5; ESR_ohm: 0.232; Value1: 0.232 ohm; VDC_V: 50; Value2: 50V; TaMin_C: -55; TaMax_C: 125; Cap_Case: 0603; SizeArea_mm2: 1.28; SizeAreaWB_mm2: 4.68; SizeX_mm: 1.6; SizeY_mm: 0.8; SizeZ_mm: 1; AEC Category: Q200; Green_Lifecycle: Active; Green_REACh: Passed
signal-integrity model Cap
simulation model Cap
footprint 0603
footprint 0603M
footprint 0603L
footprint 0603_HV
footprint 0603S
pins: 1, 2

## 06035A330JAT2A
designator C?  ValueDisplayed: 33pF  (hidden comment: 06035A330JAT2A)
CAP, CERM, 33 pF, 50 V,+/- 5%, C0G/NP0, 0603; Manufacturer: AVX; Polarized: N; CompType: Capacitor; Value: 33pF; U/M: EA; Cap_F: 0.000000000033; Tolerance_%: 5; ESR_ohm: 0.209; Value1: 0.209 ohm; VDC_V: 50; Value2: 50V; TaMin_C: -55; TaMax_C: 125; Cap_Case: 0603; SizeArea_mm2: 1.28; SizeAreaWB_mm2: 4.68; SizeX_mm: 1.6; SizeY_mm: 0.8; SizeZ_mm: 1; AEC Category: Q200; Green_Lifecycle: Active; Green_REACh: Passed
signal-integrity model Cap
simulation model Cap
footprint 0603
footprint 0603M
footprint 0603L
footprint 0603_HV
footprint 0603S
pins: 1, 2

## 06035A331JAT2A
designator C?  ValueDisplayed: 330pF  (hidden comment: 06035A331JAT2A)
CAP, CERM, 330 pF, 50 V,+/- 5%, C0G/NP0, 0603; Manufacturer: AVX; Polarized: N; CompType: Capacitor; Value: 330pF; U/M: EA; Cap_F: 0.00000000033; Tolerance_%: 5; ESR_ohm: 0.071; Value1: 0.071 ohm; VDC_V: 50; Value2: 50V; TaMin_C: -55; TaMax_C: 125; Cap_Case: 0603; SizeArea_mm2: 1.28; SizeAreaWB_mm2: 4.68; SizeX_mm: 1.6; SizeY_mm: 0.8; SizeZ_mm: 1; AEC Category: Q200; Green_Lifecycle: Active; Green_REACh: Passed
signal-integrity model Cap
simulation model Cap
footprint 0603
footprint 0603M
footprint 0603L
footprint 0603_HV
footprint 0603S
pins: 1, 2

## 06035A390JAT2A
designator C?  ValueDisplayed: 39pF  (hidden comment: 06035A390JAT2A)
CAP, CERM, 39 pF, 50 V,+/- 5%, C0G/NP0, 0603; Manufacturer: AVX; Polarized: N; CompType: Capacitor; Value: 39pF; U/M: EA; Cap_F: 0.000000000039; Tolerance_%: 5; ESR_ohm: 0.191; Value1: 0.191 ohm; VDC_V: 50; Value2: 50V; TaMin_C: -55; TaMax_C: 125; Cap_Case: 0603; SizeArea_mm2: 1.28; SizeAreaWB_mm2: 4.68; SizeX_mm: 1.6; SizeY_mm: 0.8; SizeZ_mm: 1; AEC Category: Q200; Green_Lifecycle: Active; Green_REACh: Passed
signal-integrity model Cap
simulation model Cap
footprint 0603
footprint 0603M
footprint 0603L
footprint 0603_HV
footprint 0603S
pins: 1, 2

## 06035A391JAT2A
designator C?  ValueDisplayed: 390pF  (hidden comment: 06035A391JAT2A)
CAP, CERM, 390 pF, 50 V,+/- 5%, C0G/NP0, 0603; Manufacturer: AVX; Polarized: N; CompType: Capacitor; Value: 390pF; U/M: EA; Cap_F: 0.00000000039; Tolerance_%: 5; ESR_ohm: 0.067; Value1: 0.067 ohm; VDC_V: 50; Value2: 50V; TaMin_C: -55; TaMax_C: 125; Cap_Case: 0603; SizeArea_mm2: 1.28; SizeAreaWB_mm2: 4.68; SizeX_mm: 1.6; SizeY_mm: 0.8; SizeZ_mm: 1; AEC Category: Q200; Green_Lifecycle: Not Set; Green_REACh: Incomplete
signal-integrity model Cap
simulation model Cap
footprint 0603
footprint 0603M
footprint 0603L
footprint 0603_HV
footprint 0603S
pins: 1, 2

## 06035A470JAT2A
designator C?  ValueDisplayed: 47pF  (hidden comment: 06035A470JAT2A)
CAP, CERM, 47 pF, 50 V,+/- 5%, C0G/NP0, 0603; Manufacturer: AVX; Polarized: N; CompType: Capacitor; Value: 47pF; U/M: EA; Cap_F: 0.000000000047; Tolerance_%: 5; ESR_ohm: 0.174; Value1: 0.174 ohm; VDC_V: 50; Value2: 50V; TaMin_C: -55; TaMax_C: 125; Cap_Case: 0603; SizeArea_mm2: 1.28; SizeAreaWB_mm2: 4.68; SizeX_mm: 1.6; SizeY_mm: 0.8; SizeZ_mm: 1; AEC Category: Q200; Green_Lifecycle: Active; Green_REACh: Passed
signal-integrity model Cap
simulation model Cap
footprint 0603
footprint 0603M
footprint 0603L
footprint 0603_HV
footprint 0603S
pins: 1, 2

## 06035A471JAT2A
designator C?  ValueDisplayed: 470pF  (hidden comment: 06035A471JAT2A)
CAP, CERM, 470 pF, 50 V,+/- 5%, C0G/NP0, 0603; Manufacturer: AVX; Polarized: N; CompType: Capacitor; Value: 470pF; U/M: EA; Cap_F: 0.00000000047; Tolerance_%: 5; ESR_ohm: 0.063; Value1: 0.063 ohm; VDC_V: 50; Value2: 50V; TaMin_C: -55; TaMax_C: 125; Cap_Case: 0603; SizeArea_mm2: 1.28; SizeAreaWB_mm2: 4.68; SizeX_mm: 1.6; SizeY_mm: 0.8; SizeZ_mm: 1; AEC Category: Q200; Green_Lifecycle: Active; Green_REACh: Passed
signal-integrity model Cap
simulation model Cap
footprint 0603
footprint 0603M
footprint 0603L
footprint 0603_HV
footprint 0603S
pins: 1, 2

## 06035A560FAT2A
designator C?  ValueDisplayed: 56pF  (hidden comment: 06035A560FAT2A)
CAP, CERM, 56 pF, 50 V,+/- 1%, C0G/NP0, 0603; Manufacturer: AVX; Polarized: N; CompType: Capacitor; Value: 56pF; U/M: EA; Cap_F: 0.000000000056; Tolerance_%: 1; VDC_V: 50; Value2: 50V; TaMin_C: -55; TaMax_C: 125; Cap_Case: 0603; SizeArea_mm2: 1.28; SizeAreaWB_mm2: 4.68; SizeX_mm: 1.6; SizeY_mm: 0.8; AEC Category: Q200; Green_Lifecycle: Not Set; Green_REACh: Incomplete
signal-integrity model Cap
simulation model Cap
footprint 0603
footprint 0603M
footprint 0603L
footprint 0603_HV
footprint 0603S
pins: 1, 2

## 06035A560JAT2A
designator C?  ValueDisplayed: 56pF  (hidden comment: 06035A560JAT2A)
CAP, CERM, 56 pF, 50 V,+/- 5%, C0G/NP0, 0603; Manufacturer: AVX; Polarized: N; CompType: Capacitor; Value: 56pF; U/M: EA; Cap_F: 0.000000000056; Tolerance_%: 5; ESR_ohm: 0.159; Value1: 0.159 ohm; VDC_V: 50; Value2: 50V; TaMin_C: -55; TaMax_C: 125; Cap_Case: 0603; SizeArea_mm2: 1.28; SizeAreaWB_mm2: 4.68; SizeX_mm: 1.6; SizeY_mm: 0.8; SizeZ_mm: 1; AEC Category: Q200; Green_Lifecycle: Active; Green_REACh: Passed
signal-integrity model Cap
simulation model Cap
footprint 0603
footprint 0603M
footprint 0603L
footprint 0603_HV
footprint 0603S
pins: 1, 2

## 06035A561JAT2A
designator C?  ValueDisplayed: 560pF  (hidden comment: 06035A561JAT2A)
CAP, CERM, 560 pF, 50 V,+/- 5%, C0G/NP0, 0603; Manufacturer: AVX; Polarized: N; CompType: Capacitor; Value: 560pF; U/M: EA; Cap_F: 0.00000000056; Tolerance_%: 5; ESR_ohm: 0.059; Value1: 0.059 ohm; VDC_V: 50; Value2: 50V; TaMin_C: -55; TaMax_C: 125; Cap_Case: 0603; SizeArea_mm2: 1.28; SizeAreaWB_mm2: 4.68; SizeX_mm: 1.6; SizeY_mm: 0.8; SizeZ_mm: 1; AEC Category: Q200; Green_Lifecycle: Active; Green_REACh: Passed
signal-integrity model Cap
simulation model Cap
footprint 0603
footprint 0603M
footprint 0603L
footprint 0603_HV
footprint 0603S
pins: 1, 2

## 06035A680JAT2A
designator C?  ValueDisplayed: 68pF  (hidden comment: 06035A680JAT2A)
CAP, CERM, 68 pF, 50 V,+/- 5%, C0G/NP0, 0603; Manufacturer: AVX; Polarized: N; CompType: Capacitor; Value: 68pF; U/M: EA; Cap_F: 0.000000000068; Tolerance_%: 5; ESR_ohm: 0.144; Value1: 0.144 ohm; VDC_V: 50; Value2: 50V; TaMin_C: -55; TaMax_C: 125; Cap_Case: 0603; SizeArea_mm2: 1.28; SizeAreaWB_mm2: 4.68; SizeX_mm: 1.6; SizeY_mm: 0.8; SizeZ_mm: 1; AEC Category: Q200; Green_Lifecycle: Active; Green_REACh: Passed
signal-integrity model Cap
simulation model Cap
footprint 0603
footprint 0603M
footprint 0603L
footprint 0603_HV
footprint 0603S
pins: 1, 2

## 06035A681FAT2A
designator C?  ValueDisplayed: 680pF  (hidden comment: 06035A681FAT2A)
CAP, CERM, 680 pF, 50 V,+/- 1%, C0G/NP0, 0603; Manufacturer: AVX; Polarized: N; CompType: Capacitor; Value: 680pF; U/M: EA; Cap_F: 0.00000000068; Tolerance_%: 1; VDC_V: 50; Value2: 50V; TaMin_C: -55; TaMax_C: 125; Cap_Case: 0603; SizeArea_mm2: 1.28; SizeAreaWB_mm2: 4.68; SizeX_mm: 1.6; SizeY_mm: 0.8; AEC Category: Q200; Green_Lifecycle: Not Set; Green_REACh: Incomplete
signal-integrity model Cap
simulation model Cap
footprint 0603
footprint 0603M
footprint 0603L
footprint 0603_HV
footprint 0603S
pins: 1, 2

## 06035A820JAT2A
designator C?  ValueDisplayed: 82pF  (hidden comment: 06035A820JAT2A)
CAP, CERM, 82 pF, 50 V,+/- 5%, C0G/NP0, 0603; Manufacturer: AVX; Polarized: N; CompType: Capacitor; Value: 82pF; U/M: EA; Cap_F: 0.000000000082; Tolerance_%: 5; ESR_ohm: 0.131; Value1: 0.131 ohm; VDC_V: 50; Value2: 50V; TaMin_C: -55; TaMax_C: 125; Cap_Case: 0603; SizeArea_mm2: 1.28; SizeAreaWB_mm2: 4.68; SizeX_mm: 1.6; SizeY_mm: 0.8; SizeZ_mm: 1; AEC Category: Q200; Green_Lifecycle: Active; Green_REACh: Passed
signal-integrity model Cap
simulation model Cap
footprint 0603
footprint 0603M
footprint 0603L
footprint 0603_HV
footprint 0603S
pins: 1, 2

## 06035A821JAT2A
designator C?  ValueDisplayed: 820pF  (hidden comment: 06035A821JAT2A)
CAP, CERM, 820 pF, 50 V,+/- 5%, C0G/NP0, 0603; Manufacturer: AVX; Polarized: N; CompType: Capacitor; Value: 820pF; U/M: EA; Cap_F: 0.00000000082; Tolerance_%: 5; ESR_ohm: 0.052; Value1: 0.052 ohm; VDC_V: 50; Value2: 50V; TaMin_C: -55; TaMax_C: 125; Cap_Case: 0603; SizeArea_mm2: 1.28; SizeAreaWB_mm2: 4.68; SizeX_mm: 1.6; SizeY_mm: 0.8; SizeZ_mm: 1; AEC Category: Q200; Green_Lifecycle: Not Set; Green_REACh: Incomplete
signal-integrity model Cap
simulation model Cap
footprint 0603
footprint 0603M
footprint 0603L
footprint 0603_HV
footprint 0603S
pins: 1, 2

## 06035C104KAT2A
designator C?  ValueDisplayed: 0.1µF  (hidden comment: 06035C104KAT2A)
CAP, CERM, 0.1 µF, 50 V,+/- 10%, X7R, 0603; Manufacturer: AVX; Polarized: N; CompType: Capacitor; Value: 0.1uF; U/M: EA; Cap_F: 0.0000001; Tolerance_%: 10; VDC_V: 50; Value2: 50V; TaMin_C: -55; TaMax_C: 125; Cap_Case: 0603; SizeArea_mm2: 1.28; SizeAreaWB_mm2: 4.68; SizeX_mm: 1.6; SizeY_mm: 0.8; SizeZ_mm: 1; AEC Category: Q200; Green_Lifecycle: Active; Green_REACh: Passed
signal-integrity model Cap
simulation model Cap
footprint 0603
footprint 0603M
footprint 0603L
footprint 0603_HV
footprint 0603S
pins: 1, 2

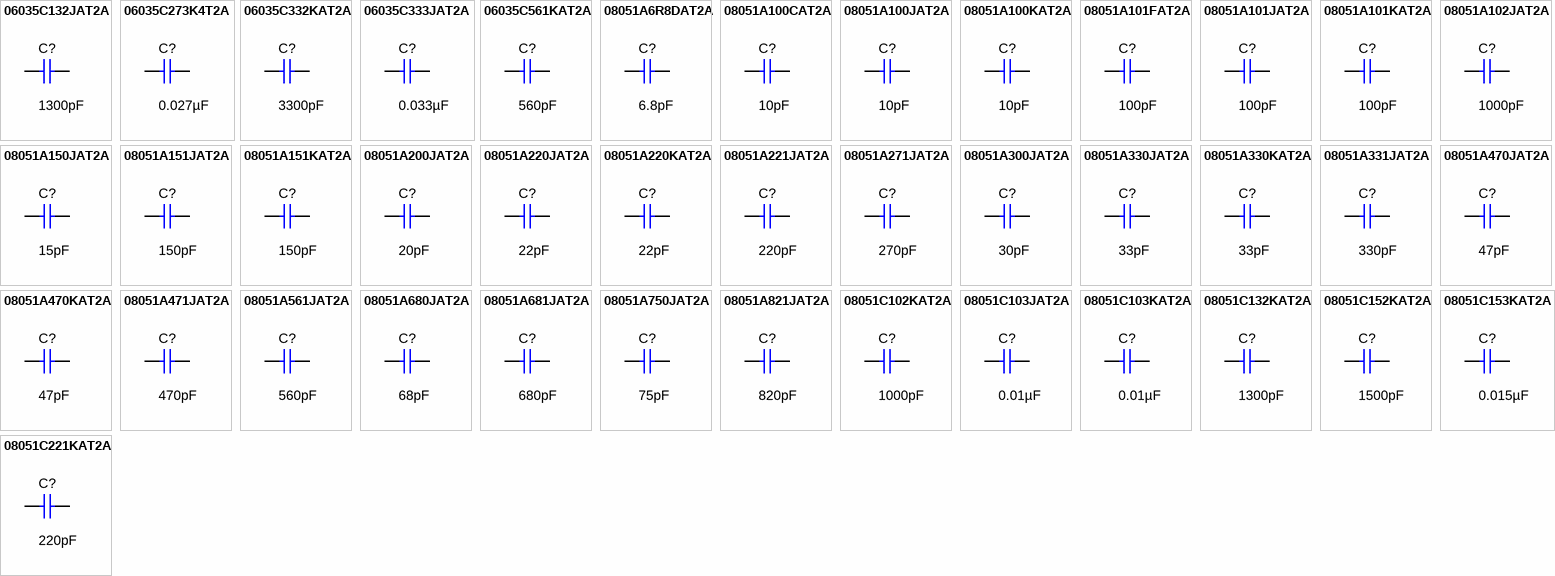
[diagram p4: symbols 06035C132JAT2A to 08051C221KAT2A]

## 06035C132JAT2A
designator C?  ValueDisplayed: 1300pF  (hidden comment: 06035C132JAT2A)
CAP, CERM, 1300 pF, 50 V,+/- 5%, X7R, 0603; Manufacturer: AVX; Polarized: N; CompType: Capacitor; Value: 1300pF; U/M: EA; Cap_F: 0.0000000013; Tolerance_%: 5; VDC_V: 50; Value2: 50V; TaMin_C: -55; TaMax_C: 125; Cap_Case: 0603; SizeArea_mm2: 1.28; SizeAreaWB_mm2: 4.68; SizeX_mm: 1.6; SizeY_mm: 0.8; SizeZ_mm: 1; AEC Category: Q200; Green_Lifecycle: Not Set; Green_REACh: Incomplete
signal-integrity model Cap
simulation model Cap
footprint 0603
footprint 0603M
footprint 0603L
footprint 0603_HV
footprint 0603S
pins: 1, 2

## 06035C273K4T2A
designator C?  ValueDisplayed: 0.027µF  (hidden comment: 06035C273K4T2A)
CAP, CERM, 0.027 µF, 50 V,+/- 10%, X7R, AEC-Q200 Grade 1, 0603; Manufacturer: AVX; Polarized: N; CompType: Capacitor; Value: 0.027uF; U/M: EA; Cap_F: 0.000000027; Tolerance_%: 10; VDC_V: 50; Value2: 50V; TaMin_C: -55; TaMax_C: 125; Cap_Case: 0603; SizeArea_mm2: 1.28; SizeAreaWB_mm2: 4.68; SizeX_mm: 1.6; SizeY_mm: 0.8; SizeZ_mm: 1; AEC Category: Q200; AEC Qualified: Y; Green_Lifecycle: Not Set; Green_REACh: Incomplete
signal-integrity model Cap
simulation model Cap
footprint 0603
footprint 0603M
footprint 0603L
footprint 0603_HV
footprint 0603S
pins: 1, 2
